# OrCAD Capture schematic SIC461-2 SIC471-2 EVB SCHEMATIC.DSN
size Custom; title: SIC462/1 SIC472/1 Demo Board 10 to 50Vin 300KHz 12V, 5V, 3V3; rev: D
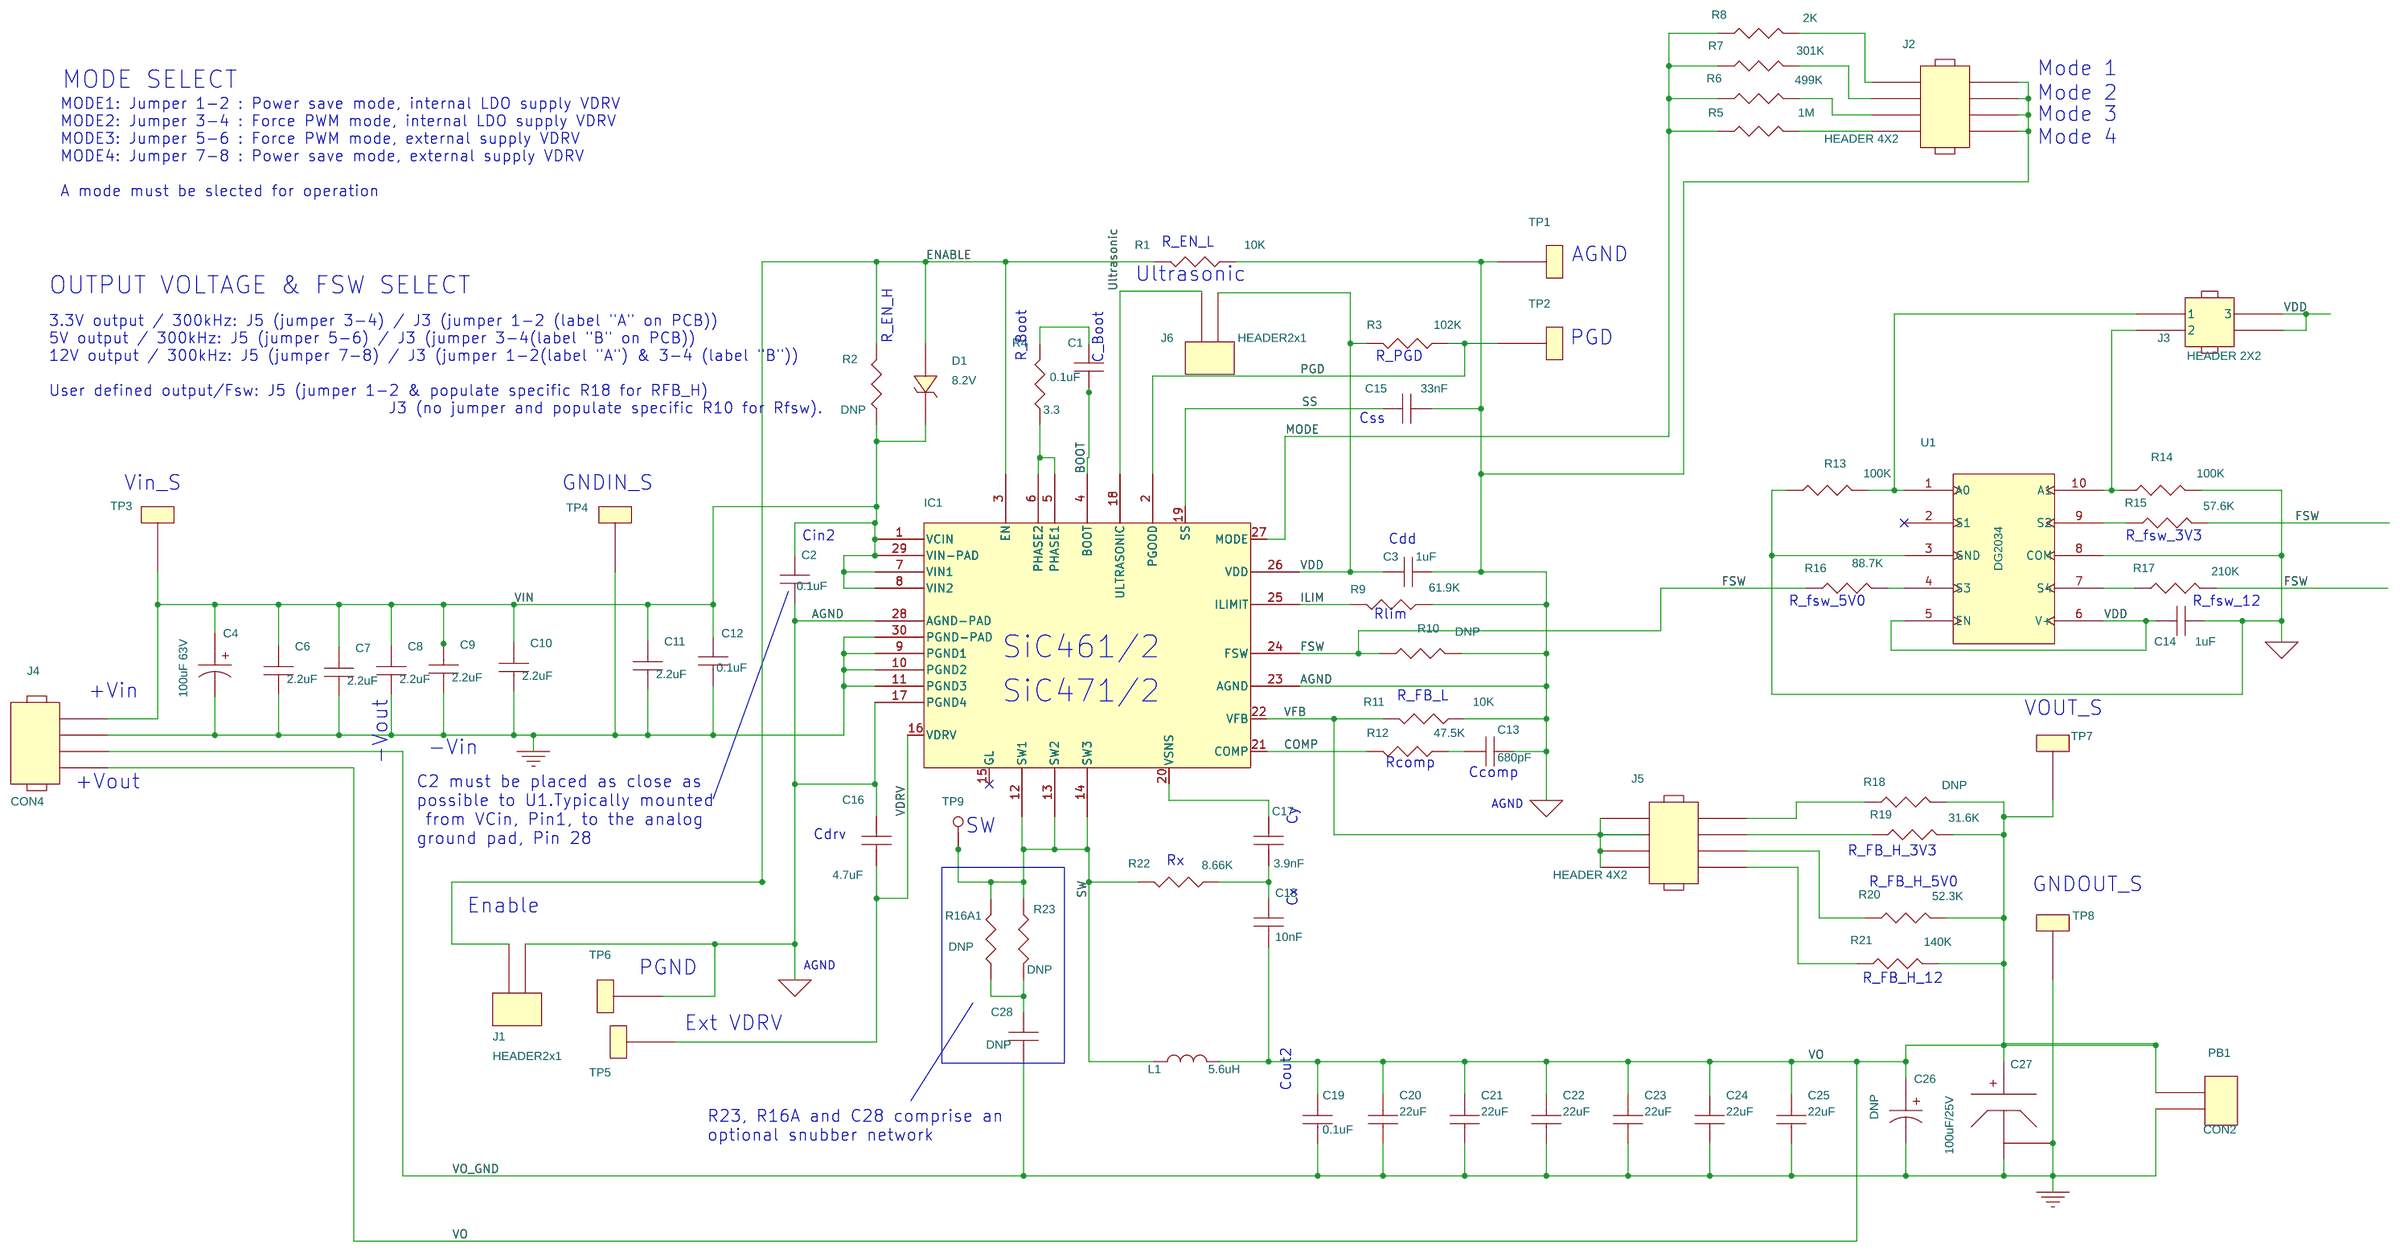
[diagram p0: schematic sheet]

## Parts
C1  0.1uF  [C0603]
C2  0.1uF  [C0603]
C3  1uF  [C0603]
C4  100uF 63V  [MAL215058101E3]
C6  2.2uF  [C1210]
C7  2.2uF  [C1210]
C8  2.2uF  [C1210]
C9  2.2uF  [C1210]
C10  2.2uF  [C1210]
C11  2.2uF  [C1210]
C12  0.1uF  [C0603]
C13  680pF  [C0603]
C14  1uF  [C0603]
C15  33nF  [C0603]
C16  4.7uF  [C0603]
C17  3.9nF  [C0603]
C18  10nF  [C0805]
C19  0.1uF  [C0603]
C20  22uF  [C1210]
C21  22uF  [C1206]
C22  22uF  [C1206]
C23  22uF  [C1206]
C24  22uF  [C1206]
C25  22uF  [C1206]
C26  DNP  [MAL215058101E3]
C27  100uF/25V  [D5L]
C28  DNP  [C0603]
D1  8.2V  [BZX384B8V2]
IC1  SiC461/2  [5mmx5mm]
J1  HEADER2x1  [minijumper2]
J2  HEADER 4X2  [minijumper2x4]
J3  HEADER 2X2  [HDR2x2]
J4  CON4  [ED120-4DS2]
J5  HEADER 4X2  [minijumper2x4]
J6  HEADER2x1  [minijumper2]
L1  5.6uH  [74439370082]
PB1  CON2  [2probe]
R1  10K  [R0603]
R2  DNP  [R0603]
R3  102K  [R0603]
R4  3.3  [R0603]
R5  1M  [R0603]
R6  499K  [R0603]
R7  301K  [R0603]
R8  2K  [R0603]
R9  61.9K  [R0603]
R10  DNP  [R0603]
R11  10K  [R0603]
R12  47.5K  [R0603]
R13  100K  [R0603]
R14  100K  [R0603]
R15  57.6K  [R0603]
R16  88.7K  [R0603]
R16A1  DNP  [R1210]
R17  210K  [R0603]
R18  DNP  [R0603]
R19  31.6K  [R0603]
R20  52.3K  [R0603]
R21  140K  [R0603]
R22  8.66K  [R0805]
R23  DNP  [R0603]
TP1  test point  [5002]
TP2  test point  [5002]
TP3  test point  [5002]
TP4  test point  [5002]
TP5  test point  [5002]
TP6  test point  [5002]
TP7  test point  [5002]
TP8  test point  [5002]
TP9  5002  [PAD040_060_SQ]
U1  DG2034  [MSOP10]

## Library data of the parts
C1 C2 C12 = CAP_NP: Ceramic Cap, 0.1uF,100volts X7R,10%,0603; DIGI-KEY: 81-GCM188R72A104KA4D; Data sheet\: http://www.mouser.com/ds/2/281/c03e-806517.pdf; Description1: Ceramic Cap, 0.1uF,100volts, X7R, 10%, 0603; Description2: Ceramic Cap, 0.1uF,100volts, X7R, 10%, 0603; DigikeyMouser: 81-GCM188R72A104KA4D; Mfr: Murata Electronics; Mfr Part Number: GCM188R72A104KA64D; PCB Footprint1: 0603; PCB Footprint2: 0603; Package: 0603; Package1: 0603; Package2: 0603
C3 C14 = CAP_NP: Ceramic Cap, 1uF,50V, X7R,0603,10%; Comment: X7R; DIGI-KEY: 963-UMK107AB7105KA-T; Data sheet\: http://www.mouser.com/ds/2/396/mlcc11_hq_e-541564.pdf; Description1: Ceramic Cap, 1uF,50V, X7R,0603,10%; Description2: Ceramic Cap, 1uF,50V, X7R,0603,10%; DigikeyMouser: 963-UMK107AB7105KA-T; Manufacturer: Taiyo Yuden; Manufacturer Part: UMK107AB7105KA-T; Manufacturer Part1: UMK107AB7105KA-T; Manufacturer Part2: UMK107AB7105KA-T; Manufacturer1: Taiyo Yuden; Manufacturer2: Taiyo Yuden; Mfr: Taiyo Yuden; Mfr Part Number: UMK107AB7105KA-T; Package: 0603; Package1: 0603; Package2: 0603; Tolerance: 10%; Voltage: 50V
C4 C26 = CAP_POL: CAP, alum, 100uF, 63volt, 105C, 10x12, 4khr; DIGI-KEY: 594-2222-150-58101; Data sheet\: http://www.mouser.com/ds/2/427/150rmi-222630.pdf; DigikeyMouser: 594-2222-150-58101; Manufacturer: Vishay; Mfr: Vishay; Part Type: CAP POL; Rating: 63V; Tolerance: 20%
C6-C11 = CAP_NP: Ceramic Cap, 2.2uF,100volts, X7R, 10%, 1210; DIGI-KEY: 81-GRM32ER72A225KA5K; Data sheet\: http://www.mouser.com/ds/2/281/c02e-2905.pdf; Description1: Ceramic Cap, 2.2uF,100volts, X7R, 10%, 1210; Description2: Ceramic Cap, 2.2uF,100volts, X7R, 10%, 1210; DigikeyMouser: 81-GRM32ER72A225KA5K; Mfr: Murata Electronics; Mfr Part Number: GRM32ER72A225KA35K
C13 = CAP_NP: MLCC - SMD/SMT 0603 560pF 50volts C0G 5% 0603; Comment: COG; DIGI-KEY: 77-VJ0603A561JXACBC; Data sheet\: http://www.mouser.com/ds/2/427/vjw1bcbascomseries-223529.pdf; Description1: MLCC - SMD/SMT 0603 560pF 50volts C0G 5% 0603; Description2: MLCC - SMD/SMT 0603 560pF 50volts C0G 5% 0603; DigikeyMouser: 77-VJ0603A561JXACBC; Manufacturer: Vishay; Manufacturer Part: VJ0603A561JXACW1BC; Manufacturer Part1: VJ0603A561JXACW1BC; Manufacturer Part2: VJ0603A561JXACW1BC; Manufacturer1: Vishay; Manufacturer2: Vishay; Mfr: Vishay; Mfr Part Number: VJ0603A561JXACW1BC; Package: 0603; Package1: 0603; Package2: 0603; Tolerance: 5%; Value1: 560p; Value2: 560p; Voltage: 50V
C15 = CAP_NP: Ceramic Cap, 0.033uF,50V,X7R,0603,10%; Comment: X7R; DIGI-KEY: 77-VJ0603Y333KXACBC; Data sheet\: http://www.mouser.com/ds/2/427/vjw1bcbascomseries-223529.pdf; Description1: Ceramic Cap, 0.033uF,50V,X7R,0603,10%; Description2: Ceramic Cap, 0.033uF,50V,X7R,0603,10%; DigikeyMouser: 77-VJ0603Y333KXACBC; Manufacturer: Vishay; Manufacturer Part: VJ0603Y333KXACW1BC; Manufacturer Part1: VJ0603Y333KXACW1BC; Manufacturer Part2: VJ0603Y333KXACW1BC; Manufacturer1: Vishay; Manufacturer2: Vishay; Mfr: Vishay / Vitramon; Mfr Part Number: VJ0603Y333KXACW1BC; Package: 0603; Package1: 0603; Package2: 0603; Tolerance: 10%; Voltage: 50V
C16 = CAP_NP: Ceramic Cap, 4.7uF,25V,X6S,10%,0603; Comment: X6S; DIGI-KEY: 81-GRM188C81E475KE1D; Data sheet\: http://www.mouser.com/ds/2/281/c02e-2905.pdf; Description1: Ceramic Cap, 4.7uF,25V,X6S,10%,0603; Description2: Ceramic Cap, 4.7uF,25V,X6S,10%,0603; DigikeyMouser: 81-GRM188C81E475KE1D; Mfr: Murata; Mfr Part Number: GRM188C81E475KE11D; Tolerance: 10%; Voltage: 25V
C17 = CAP_NP: Ceramic Cap, 2200pF,100V,X7R,0603, 5%; Comment: X7R; DIGI-KEY: 77-VJ0603Y222JXBCBC; Data sheet\: http://www.mouser.com/ds/2/427/vjw1bcbascomseries-223529.pdf; Description1: Ceramic Cap, 2200pF,100V,X7R,0603, 5%; Description2: Ceramic Cap, 2200pF,100V,X7R,0603, 5%; DigikeyMouser: 77-VJ0603Y222JXBCBC; Manufacturer: Vishay; Manufacturer Part: VJ0603Y222JXBCW1BC; Manufacturer Part1: VJ0603Y222JXBCW1BC; Manufacturer Part2: VJ0603Y222JXBCW1BC; Manufacturer1: Vishay; Manufacturer2: Vishay; Mfr: Vishay; Mfr Part Number: VJ0603Y222JXBCW1BC; Package: 0603; Package1: 0603; Package2: 0603; Tolerance: 5%; Value1: 2.2nF; Value2: 2.2nF; Voltage: 100V
C18 = CAP_NP: Ceramic Cap, 560pF,100V,X7R,0805, 10%; Comment: X7R; DIGI-KEY: 77-VJ0805Y561KXBPBC; Data sheet\: http://www.mouser.com/ds/2/427/vjw1bcbascomseries-223529.pdf; Description1: Ceramic Cap, 560pF,100V,X7R,0805, 10%; Description2: Ceramic Cap, 560pF,100V,X7R,0805, 10%; DigikeyMouser: 77-VJ0805Y561KXBPBC; Manufacturer: Vishay; Manufacturer Part: VJ0805Y561KXBPW1BC; Manufacturer Part1: VJ0805Y561KXBPW1BC; Manufacturer Part2: VJ0805Y561KXBPW1BC; Manufacturer1: Vishay; Manufacturer2: Vishay; Mfr: Vishay / Vitramon; Mfr Part Number: VJ0805Y561KXBPW1BC; Package: 0805; Package1: 0805; Package2: 0805; Tolerance: 10%; Value1: 560pF; Value2: 560pF; Voltage: 100V
C19 = CAP_NP: Ceramic Cap, 0.1uF,100volts,X7R,10%,0603; Comment: X7S; Data sheet\: http://www.digikey.com/product-detail/en/C1608X7S2A104K080AB/445-5201-2-ND/2116317; Description1: Ceramic Cap, 0.1uF,100volts,X7R,10%,0603; Description2: Ceramic Cap, 0.1uF,100volts,X7R,10%,0603; DigikeyMouser: 445-5201-2-ND; Manufacturer: Vishay; Manufacturer Part: VJ0603Y104KXB; Manufacturer Part1: VJ0603Y104KXB; Manufacturer Part2: VJ0603Y104KXB; Manufacturer1: Vishay; Manufacturer2: Vishay; Mfr: TDK Corporation; Mfr Part Number: C1608X7S2A104K080AB; Package: 0603; Package1: 0603; Package2: 0603; Tolerance: 10%; Voltage: 100V
C20-C25 = CAP_NP: Ceramic Cap, 22uF,25volts,X6S,20%,1206; Comment: X6S; DIGI-KEY: 81-GRM31CC81E226ME1L; Data sheet\: http://www.mouser.com/ds/2/281/GRM31CC81E226ME11-01-1064917.pdf; Description1: Ceramic Cap, 22uF,25volts,X6S,20%,1206; Description2: Ceramic Cap, 22uF,25volts,X6S,20%,1206; DigikeyMouser: 81-GRM31CC81E226ME1L; Mfr: Murata Electronics; Mfr Part Number: GRM31CC81E226ME11L; Tolerance: 20%; Voltage: 25V
C27 = CAP,_TA-P,V,470u,_2V_0: Polymer SMD 20volts 100uF ESR 55mohm 7343; DIGI-KEY: 667-20TQC100MYF; Data sheet\: http://www.mouser.com/ds/2/315/AAA8000C54-931458.pdf; DigikeyMouser: 667-20TQC100MYF; Mfr: Panasonic; Mfr Part Number: 20TQC100MYF
C28 = CAP_NP: Comment: X7S; Data sheet\: http://www.digikey.com/product-detail/en/C1608X7S2A104K080AB/445-5201-2-ND/2116317; DigikeyMouser: 445-5201-2-ND; Mfr: TDK Corporation; Mfr Part Number: C1608X7S2A104K080AB; Package: 0603; Package1: 0603; Package2: 0603; Tolerance: 10%; Voltage: 100V
D1 = DIODE_ZENER: Zener Diodes 8.2 Volt 0.2W 2%; DIGI-KEY: 78-BZX384B8V2-E3-08; Data sheet\: http://www.mouser.com/ds/2/427/bzx384-58924.pdf; Description1: Zener Diodes 8.2 Volt 0.2W 2%; Description2: Zener Diodes 8.2 Volt 0.2W 2%; DigikeyMouser: 78-BZX384B8V2-E3-08; Mfr: Vishay; Mfr Part Number: BZX384B8V2-E3-08
IC1 = SiC462CD-T1-GE3_37: 4.5~60V, 4A, High Voltage microBuck; DIGI-KEY: 78-SIC463ED-T1-GE3; Data sheet\: http://www.mouser.com/ds/2/427/sic462-1061838.pdf; Description1: 4.5~60V, 4A, High Voltage microBuck; Description2: 4.5~60V, 4A, High Voltage microBuck; DigikeyMouser: 78-SIC463ED-T1-GE3; Man: Vishay; Man Part Number: SIC463CD-T1-GE3; Man Part Number1: SIC463CD-T1-GE3; Man Part Number2: SIC463CD-T1-GE3; Man1: Vishay; Man2: Vishay; Mfr: Vishay; Mfr Part Number: SIC463ED-T1-GE3; Value1: SiC463; Value2: SiC463
J1 J6 PB1 = CON2
J2 J5 = HEADER_4X2: CONN HEADER 8POS .100 STR 15AU; DIGI-KEY: 609-3371-ND; Data sheet\: https://cdn.amphenol-icc.com/media/wysiwyg/files/drawing/67996.pdf; Description1: CONN HEADER 8POS .100 STR 15AU; Description2: CONN HEADER 8POS .100 STR 15AU; DigikeyMouser: 609-3371-ND; Mfr: Amphenol FCI; Mfr Part Number: 68602-208HLF
J3 = HEADER_2X2_1: CONN HEADER .050" 4POS DL PCB AU; DIGI-KEY: S9015E-02-ND; Data sheet\: https://media.digikey.com/pdf/Data%20Sheets/Sullins%20PDFs/GRPB_%20_2VWVN-RC%2010954-C.pdf; Description1: CONN HEADER .050" 4POS DL PCB AU; Description2: CONN HEADER .050" 4POS DL PCB AU; DigikeyMouser: S9015E-02-ND; Mfr: Sullins; Mfr Part Number: GRPB022VWVN-RC
J4 = HEADER_4: TERMINAL BLOCK 3.81MM Horz 4POS; DIGI-KEY: 649-220327-D041B01LF; Data sheet\: http://www.mouser.com/ds/2/18/20020327-941783.pdf; Description1: T; DigikeyMouser: 649-220327-D041B01LF; Man: Amphenol Anytek; Mfr: Amphenol Anytek; Mfr Part Number: 20020327-D041B01LF; Rating: 10A
L1 = IND: INDUCTOR, 8.2uH,20%,6.5m DCR,44A Saturation 16x15x10; Current: 18A; DIGI-KEY: 710-74439370082; Data sheet\: https://www.mouser.com/datasheet/2/445/74439370082-1020900.pdf; Description1: INDUCTOR, 8.2uH,20%,6.5m DCR,44A Saturation 16x15x10; Description2: INDUCTOR, 8.2uH,20%,6.5m DCR,44A Saturation 16x15x10; DigikeyMouser: 710-74439370082; Manufacturer: Wurth; Manufacturer1: Wurth; Manufacturer2: Wurth; Mfr: Wurth; Value1: 8.2uH
R1 R11 = RESISTOR: SMD,10K,1%,0603; DIGI-KEY: 71-CRCW0603-10K; Data sheet\: http://www.mouser.com/ds/2/427/dcrcwe3-109170.pdf; Description1: SMD,10K,1%,0603; Description2: SMD,10K,1%,0603; DigikeyMouser: 71-CRCW0603-10K; Manufacturer: Vishay; Manufacturer Part: CRCW060310K0FKTA; Manufacturer Part1: CRCW060310K0FKTA; Manufacturer Part2: CRCW060310K0FKTA; Manufacturer1: Vishay; Manufacturer2: Vishay; Mfr: Vishay Dale; Mfr Part Number: CRCW060310K0FKTA; Package: 0603; Package1: 0603; Package2: 0603; Tolerance: 1%
R2 = RESISTOR: SMD,560K,1%,0603; DIGI-KEY: 71-CRCW0603-560K-E3; Data sheet\: http://www.mouser.com/ds/2/427/dcrcwe3-109170.pdf; Description1: SMD,560K,1%,0603; Description2: SMD,560K,1%,0603; DigikeyMouser: 71-CRCW0603-560K-E3; Man: Vishay; Man Part Number: CRCW0603560KFKEA; Man Part Number1: CRCW0603560KFKEA; Man Part Number2: CRCW0603560KFKEA; Man1: Vishay; Man2: Vishay; Manufacturer: Vishay; Manufacturer Part: CRCW0603560KFKTA; Manufacturer Part1: CRCW0603560KFKTA; Manufacturer Part2: CRCW0603560KFKTA; Manufacturer1: Vishay; Manufacturer2: Vishay; Mfr: Vishay; Mfr Part Number: CRCW0603560KFKEA; PCB Footprint1: 0603; PCB Footprint2: 0603; Package: 0603; Package1: 0603; Package2: 0603; Value1: 560K; Value2: 560K
R3 = RESISTOR: SMD,102K,1%,0603; DIGI-KEY: 71-CRCW0603-102K-E3; Data sheet\: http://www.mouser.com/ds/2/427/dcrcwe3-109170.pdf; Description1: SMD,102K,1%,0603; Description2: SMD,102K,1%,0603; DigikeyMouser: 71-CRCW0603-102K-E3; Man: Vishay; Man Part Number: CRCW0603102KFKEA; Man Part Number1: CRCW0603102KFKEA; Man Part Number2: CRCW0603102KFKEA; Man1: Vishay; Man2: Vishay; Manufacturer: Vishay; Manufacturer Part: CRCW0603102KFKEA; Manufacturer Part1: CRCW0603102KFKEA; Manufacturer Part2: CRCW0603102KFKEA; Manufacturer1: Vishay; Manufacturer2: Vishay; Mfr: Vishay; Mfr Part Number: CRCW0603102KFKEA; PCB Footprint1: 0603; PCB Footprint2: 0603; Package: 0603; Package1: 0603; Package2: 0603
R4 = RESISTOR: SMD,3.3Ohm, 1% 0603; DIGI-KEY: 71-CRCW06033R30FKEA; Data sheet\: http://www.mouser.com/ds/2/427/dcrcwe3-109170.pdf; Description1: SMD,3.3Ohm, 1% 0603; Description2: SMD,3.3Ohm, 1% 0603; DigikeyMouser: 71-CRCW06033R30FKEA; Man: Vishay; Man Part Number: CRCW06033R30FKEA; Man Part Number1: CRCW06033R30FKEA; Man Part Number2: CRCW06033R30FKEA; Man1: Vishay; Man2: Vishay; Manufacturer: Vishay; Manufacturer Part: CRCW06030000ZSTA; Manufacturer Part1: CRCW06030000ZSTA; Manufacturer Part2: CRCW06030000ZSTA; Manufacturer1: Vishay; Manufacturer2: Vishay; Mfr: Vishay; Mfr Part Number: CRCW06033R30FKEA; PCB Footprint1: 0603; PCB Footprint2: 0603; Package: 0603; Package1: 0603; Package2: 0603
R5 = RESISTOR: SMD,1000K,1%,0603; DIGI-KEY: 71-RCG06031M00FKEA; Data sheet\: http://www.mouser.com/ds/2/427/rcge3-254226.pdf; Description1: SMD,1000K,1%,0603; Description2: SMD,1000K,1%,0603; DigikeyMouser: 71-RCG06031M00FKEA; Manufacturer: Vishay; Manufacturer Part: RCG06031M00FKEA; Manufacturer Part1: RCG06031M00FKEA; Manufacturer Part2: RCG06031M00FKEA; Manufacturer1: Vishay; Manufacturer2: Vishay; Mfr: Vishay Dale; Mfr Part Number: RCG06031M00FKEA; Package: 0603; Package1: 0603; Package2: 0603; Tolerance: 1%
R6 = RESISTOR: SMD,499K,1%,0603; DIGI-KEY: 71-CRCW0603-499K-E3; Data sheet\: http://www.mouser.com/ds/2/427/dcrcwe3-109170.pdf; Description1: SMD,499K,1%,0603; Description2: SMD,499K,1%,0603; DigikeyMouser: 71-CRCW0603-499K-E3; Manufacturer: Vishay; Manufacturer Part: CRCW0603499KFKEA; Manufacturer Part1: CRCW0603499KFKEA; Manufacturer Part2: CRCW0603499KFKEA; Manufacturer1: Vishay; Manufacturer2: Vishay; Mfr: Vishay Dale; Mfr Part Number: CRCW0603499KFKEA; Package: 0603; Package1: 0603; Package2: 0603; Tolerance: 1%
R7 = RESISTOR: SMD,301K,1%,0603; DIGI-KEY: 71-CRCW0603-301K-E3; Data sheet\: http://www.mouser.com/ds/2/427/dcrcwe3-109170.pdf; Description1: SMD,301K,1%,0603; Description2: SMD,301K,1%,0603; DigikeyMouser: 71-CRCW0603-301K-E3; Manufacturer: Vishay; Manufacturer Part: CRCW0603301KFKEA; Manufacturer Part1: CRCW0603301KFKEA; Manufacturer Part2: CRCW0603301KFKEA; Manufacturer1: Vishay; Manufacturer2: Vishay; Mfr: Vishay Dale; Mfr Part Number: CRCW0603301KFKEA; Package: 0603; Package1: 0603; Package2: 0603; Tolerance: 1%
R8 = RESISTOR: SMD,2K,1%,0603; DIGI-KEY: 71-CRCW06032K00FKEB; Data sheet\: http://www.mouser.com/ds/2/427/dcrcwe3-109170.pdf; Description1: SMD,2K,1%,0603; Description2: SMD,2K,1%,0603; DigikeyMouser: 71-CRCW06032K00FKEB; Manufacturer: Vishay; Manufacturer Part: CRCW06032K00FKEB; Manufacturer Part1: CRCW06032K00FKEB; Manufacturer Part2: CRCW06032K00FKEB; Manufacturer1: Vishay; Manufacturer2: Vishay; Mfr: Vishay Dale; Mfr Part Number: CRCW06032K00FKEB; Package: 0603; Package1: 0603; Package2: 0603; Tolerance: 1%
R9 = RESISTOR: SMD,37.4K,1%,0603; DIGI-KEY: 71-CRCW0603-37.4K-E3; Data sheet\: http://www.digikey.com/product-detail/en/vishay-dale/CRCW04024K64FKED/541-4.64KLCT-ND/1183198; Description1: SMD,37.4K,1%,0603; Description2: SMD,37.4K,1%,0603; DigikeyMouser: 71-CRCW0603-37.4K-E3; Manufacturer: Vishay; Manufacturer Part: CRCW060337K4FKEA; Manufacturer Part1: CRCW060337K4FKEA; Manufacturer Part2: CRCW060337K4FKEA; Manufacturer1: Vishay; Manufacturer2: Vishay; Mfr: Vishay Dale; Mfr Part Number: CRCW060337K4FKEA; Package: 0603; Package1: 0603; Package2: 0603; Tolerance: 1%; Value1: 37.4K; Value2: 37.4K
R10 R13 R14 R18 = RESISTOR: SMD 1,10W 31.6K Ohms 1% 0603; DIGI-KEY: 71-CRCW0603-31.6K-E3; Data sheet\: http://www.mouser.com/ds/2/427/dcrcwe3-109170.pdf; Description1: SMD 1,10W 31.6K Ohms 1% 0603; Description2: SMD 1,10W 31.6K Ohms 1% 0603; DigikeyMouser: 71-CRCW0603-31.6K-E3; Manufacturer: Vishay; Manufacturer Part: CRCW060331K6FKEA; Manufacturer Part1: CRCW060331K6FKEA; Manufacturer Part2: CRCW060331K6FKEA; Manufacturer1: Vishay; Manufacturer2: Vishay; Mfr: Vishay Dale; Mfr Part Number: CRCW060331K6FKEA; Package: 0603; Package1: 0603; Package2: 0603; Tolerance: 1%; Value1: 31.6K; Value2: 31.6K
R12 = RESISTOR: SMD,102K,1%,0603; DIGI-KEY: 71-CRCW0603-102K-E3; Data sheet\: http://www.mouser.com/ds/2/427/dcrcwe3-109170.pdf; Description1: SMD,102K,1%,0603; Description2: SMD,102K,1%,0603; DigikeyMouser: 71-CRCW0603-102K-E3; Man: Vishay; Man Part Number: CRCW0603102KFKEA; Man Part Number1: CRCW0603102KFKEA; Man Part Number2: CRCW0603102KFKEA; Man1: Vishay; Man2: Vishay; Manufacturer: Vishay; Manufacturer Part: CRCW0603102KFKEA; Manufacturer Part1: CRCW0603102KFKEA; Manufacturer Part2: CRCW0603102KFKEA; Manufacturer1: Vishay; Manufacturer2: Vishay; Mfr: Vishay; Mfr Part Number: CRCW0603102KFKEA; PCB Footprint1: 0603; PCB Footprint2: 0603; Package: 0603; Package1: 0603; Package2: 0603; Value1: 102K; Value2: 102K
R15 R17 = RESISTOR: SMD 1,10W 43.2K Ohms 1% 0603; DIGI-KEY: 71-CRCW0603-43.2K-E3; Data sheet\: http://www.mouser.com/ds/2/427/dcrcwe3-109170.pdf; Description1: SMD 1,10W 43.2K Ohms 1% 0603; Description2: SMD 1,10W 43.2K Ohms 1% 0603; DigikeyMouser: 71-CRCW0603-43.2K-E3; Manufacturer: Vishay; Manufacturer Part: 71-CRCW0603-43.2K-E3; Manufacturer Part1: 71-CRCW0603-43.2K-E3; Manufacturer Part2: 71-CRCW0603-43.2K-E3; Manufacturer1: Vishay; Manufacturer2: Vishay; Mfr: Vishay Dale; Mfr Part Number: CRCW060343K2FKEA; Package: 0603; Package1: 0603; Package2: 0603; Tolerance: 1%; Value1: 43.2K; Value2: 43.2K
R16 = RESISTOR: SMD 1,10W 64.9K Ohms 1%; DIGI-KEY: 71-CRCW0603-64.9K-E3; Data sheet\: http://www.mouser.com/ds/2/427/dcrcwe3-109170.pdf; Description1: SMD 1,10W 64.9K Ohms 1%; Description2: SMD 1,10W 64.9K Ohms 1%; DigikeyMouser: 71-CRCW0603-64.9K-E3; Manufacturer: Vishay; Manufacturer Part: CRCW060364K9FKEA; Manufacturer Part1: CRCW060364K9FKEA; Manufacturer Part2: CRCW060364K9FKEA; Manufacturer1: Vishay; Manufacturer2: Vishay; Mfr: Vishay Dale; Mfr Part Number: CRCW060364K9FKEA; Package: 0603; Package1: 0603; Package2: 0603; Tolerance: 1%; Value1: 69.4K; Value2: 69.4K
R16A1 = RESISTOR: SMD,1.0K,1%,1210; DIGI-KEY: 71-CRCW12101K00FKEAH; Data sheet\: http://www.mouser.com/ds/2/427/crcwhpe3-46056.pdf; DigikeyMouser: 71-CRCW12101K00FKEAH; Manufacturer: Vishay; Manufacturer Part: CRCW12101K00FKEAHP; Mfr: Vishay Dale; Mfr Part Number: CRCW12101K00FKEAHP; Package: 1210; Tolerance: 1%
R19 = RESISTOR: SMD 1,10W 31.6K Ohms 1% 0603; DIGI-KEY: 71-CRCW0603-31.6K-E3; Data sheet\: http://www.mouser.com/ds/2/427/dcrcwe3-109170.pdf; Description1: SMD 1,10W 31.6K Ohms 1% 0603; Description2: SMD 1,10W 31.6K Ohms 1% 0603; DigikeyMouser: 71-CRCW0603-31.6K-E3; Manufacturer: Vishay; Manufacturer Part: CRCW060331K6FKEA; Manufacturer Part1: CRCW060331K6FKEA; Manufacturer Part2: CRCW060331K6FKEA; Manufacturer1: Vishay; Manufacturer2: Vishay; Mfr: Vishay Dale; Mfr Part Number: CRCW060331K6FKEA; Package: 0603; Package1: 0603; Package2: 0603; Tolerance: 1%
R20 = RESISTOR: SMD 1,10W 52.3 kOhms 1% 0603; DIGI-KEY: 71-CRCW0603-52.3K-E3; Data sheet\: http://www.mouser.com/ds/2/427/dcrcwe3-109170.pdf; Description1: SMD 1,10W 52.3 kOhms 1% 0603; Description2: SMD 1,10W 52.3 kOhms 1% 0603; DigikeyMouser: 71-CRCW0603-52.3K-E3; Manufacturer: Vishay; Manufacturer Part: CRCW060352K3FKEA; Manufacturer Part1: CRCW060352K3FKEA; Manufacturer Part2: CRCW060352K3FKEA; Manufacturer1: Vishay; Manufacturer2: Vishay; Mfr: Vishay Dale; Mfr Part Number: CRCW060352K3FKEA; Package: 0603; Package1: 0603; Package2: 0603; Tolerance: 1%
R21 = RESISTOR: SMD 1,10W 52.3 kOhms 1% 0603; DIGI-KEY: 71-CRCW0603-52.3K-E3; Data sheet\: http://www.mouser.com/ds/2/427/dcrcwe3-109170.pdf; Description1: SMD 1,10W 52.3 kOhms 1% 0603; Description2: SMD 1,10W 52.3 kOhms 1% 0603; DigikeyMouser: 71-CRCW0603-52.3K-E3; Manufacturer: Vishay; Manufacturer Part: CRCW060352K3FKEA; Manufacturer Part1: CRCW060352K3FKEA; Manufacturer Part2: CRCW060352K3FKEA; Manufacturer1: Vishay; Manufacturer2: Vishay; Mfr: Vishay Dale; Mfr Part Number: CRCW060352K3FKEA; Package: 0603; Package1: 0603; Package2: 0603; Tolerance: 1%; Value1: 52.3K; Value2: 52.3K
R22 = RESISTOR: Resistors - SMD 1/8watt 49.9Kohms 1% 0805; DIGI-KEY: 71-CRCW0805-49.9K-E3; Data sheet\: http://www.mouser.com/ds/2/427/dcrcw-72725.pdf; Description1: Resistors - SMD 1/8watt 49.9Kohms 1% 0805; Description2: Resistors - SMD 1/8watt 49.9KKohms 1% 0805; DigikeyMouser: 71-CRCW0805-49.9K-E3; Mfr: Vishay Dale; Mfr Part Number: CRCW080522K6FKEA; Tolerance: 1%
R23 = RESISTOR: Data sheet\: http://www.digikey.com/product-detail/en/vishay-dale/CRCW04024K64FKED/541-4.64KLCT-ND/1183198; DigikeyMouser: 541-4.64KLCT-ND; Mfr: Vishay Dale; Mfr Part Number: CRCW04024K64FKED; Package: 0603; Package1: 0603; Package2: 0603; Tolerance: 1%
TP1-TP8 = TEST_POINT: Circuit Board Hardware-PCB TEST POINT WHITE; Description1: Circuit Board Hardware-PCB TEST POINT WHITE; Description2: Circuit Board Hardware-PCB TEST POINT WHITE; Man: Keystone Electronics; Man Part Number1: Keystone Electronics 5002; Man Part Number2: Keystone Electronics 5002; Man1: Keystone Electronics; Man2: Keystone Electronics; Manufacturer: Keystone Electronics; Manufacturer1: Keystone Electronics; Manufacturer2: Keystone Electronics
TP9 = TP_0: TST PNT,WHT INSL,0.050"ID; DIGI-KEY: 5002K-ND; Mfr: KEYSTONE ELECTRONICS CORP.; Part Type: TP
U1 = DG2034M

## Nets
GND: C4.2 C6.1 C7.1 C8.1 C9.1 C10.1 C11.1 C12.2 C19.1 C20.1 C21.1 C22.1 C23.1 C24.1 C25.1 C26.2 C27.2 C27.3 C28.2 IC1.9(PGND1) IC1.10(PGND2) IC1.11(PGND3) IC1.30(PGND-PAD) J4.2 J4.3 PB1.2 TP4.1 TP8.1
GND_SIGNAL: C2.2 C3.1 C13.1 C14.1 C15.2 C16.1 IC1.17(PGND4) IC1.23(AGND) IC1.28(AGND-PAD) J1.1 J2.1 J2.3 J2.5 J2.7 R1.1 R9.1 R10.2 R11.1 R13.1 R14.2 TP1.1 TP6.1 U1.3(GND) U1.8(COM)
VDD: C3.2 C14.2 IC1.26(VDD) J3.1(3) J3.3 J6.1 R3.2 U1.5(EN) U1.6(V+)
VIN: C2.1 C4.1 C6.2 C7.2 C8.2 C9.2 C10.2 C11.2 C12.1 D1.1(CATHODE) IC1.1(VCIN) IC1.7(VIN1) IC1.8(VIN2) IC1.29(VIN-PAD) J4.1 R2.1 TP3.1
BOOT: C1.2 IC1.4(BOOT)
COMP: IC1.21(COMP) R12.2
ENABLE: D1.2(ANODE) IC1.3(EN) J1.2 R1.2 R2.2
FSW: IC1.24(FSW) R10.1 R15.2 R16.1 R17.2
ILIM: IC1.25(ILIMIT) R9.2
MODE: IC1.27(MODE) R5.1 R6.1 R7.1 R8.1
PGD: IC1.2(PGOOD) R3.1 TP2.1
SS: C15.1 IC1.19(SS)
SW: IC1.12(SW1) IC1.13(SW2) IC1.14(SW3) L1.2(B) R16A1.1 R22.2 R23.1 TP9.1
Ultrasonic: IC1.18(ULTRASONIC) J6.2
VDRV: C16.2 IC1.16(VDRV) TP5.1
VFB: IC1.22(VFB) J5.2 J5.4 J5.6 J5.8 R11.2
VO: C18.2 C19.2 C20.2 C21.2 C22.2 C23.2 C24.2 C25.2 C26.1 C27.1 J4.4 L1.1(A) PB1.1 R18.2 R19.2 R20.2 R21.2 TP7.1
N16770186: IC1.5(PHASE1) IC1.6(PHASE2) R4.1
N16770229: C1.1 R4.2
N16771868: C13.2 R12.1
N16812890: C28.1 R16A1.2 R23.2
N16842327: C17.1 IC1.20(VSNS)
N16874863: C17.2 C18.1 R22.1
N16925691: J3.4(2) R14.1 U1.10(A1)
N16925729: J3.2(1) R13.2 U1.1(A0)
N16925754: R15.1 U1.9(S2)
N16927026: J2.2 R8.2
N16927057: J2.4 R7.2
N16927078: J2.6 R6.2
N16927108: J2.8 R5.2
N16928182: R16.2 U1.4(S3)
N16928193: R17.1 U1.7(S4)
N16929893: J5.3 R19.1
N16929909: J5.1 R18.1
N16931055: J5.5 R20.1
N16931143: J5.7 R21.1

Not connected (* = marked no-connect by the designer): IC1 15(GL)*; U1 2(S1)*

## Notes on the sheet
- Mode 1
- MODE SELECT
- Mode 2
- MODE1: Jumper 1-2 : Power save mode, internal LDO supply VDRV
  MODE2: Jumper 3-4 : Force PWM mode, internal LDO supply VDRV
  MODE3: Jumper 5-6 : Force PWM mode, external supply VDRV
  MODE4: Jumper 7-8 : Power save mode, external supply VDRV
  A mode must be slected for operation
- Mode 3
- Mode 4
- R_EN_L
- AGND
- OUTPUT VOLTAGE & FSW SELECT
- Ultrasonic
- 3.3V output / 300kHz: J5 (jumper 3-4) / J3 (jumper 1-2 (label "A" on PCB))
  5V output / 300kHz: J5 (jumper 5-6) / J3 (jumper 3-4(label "B" on PCB))
  12V output / 300kHz: J5 (jumper 7-8) / J3 (jumper 1-2(label "A") & 3-4 (label "B"))
  User defined output/Fsw: J5 (jumper 1-2 & populate specific R18 for RFB_H)
                                           J3 (no jumper and populate specific R10 for Rfsw).
- PGD
- R_EN_H
- R_PGD
- R_Boot
- C_Boot
- Css
- Vin_S
- GNDIN_S
- Cin2
- Cdd
- R_fsw_3V3
- R_fsw_5V0
- R_fsw_12
- Rlim
- SiC461/2
- +Vin
- SiC471/2
- R_FB_L
- VOUT_S
- -Vin
- Rcomp
- +Vout
- -Vout
- C2 must be placed as close as
  possible to U1.Typically mounted
   from VCin, Pin1, to the analog
  ground pad, Pin 28
- Ccomp
- SW
- AGND
- Cdrv
- Cy
- Rx
- R_FB_H_3V3
- R_FB_H_5V0
- GNDOUT_S
- Enable
- Cx
- PGND
- AGND
- R_FB_H_12
- Ext VDRV
- Cout2
- R23, R16A and C28 comprise an
  optional snubber network
